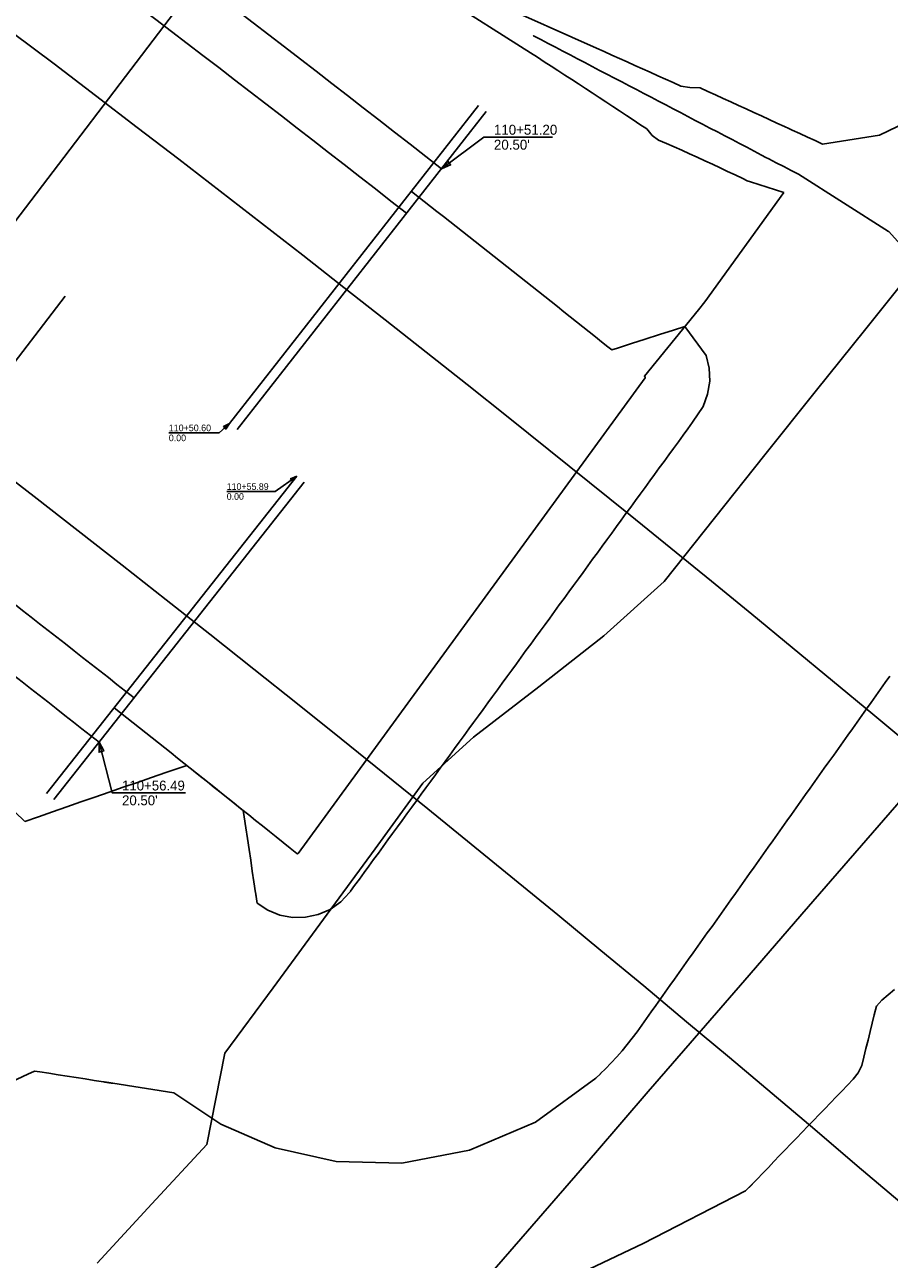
# Model space of a CAD drawing. Extents: x 1006695 to 1009377, y 1883329 to 1886115.
# Drawn here: x 1007771.4 to 1007824.9, y 1884757.7 to 1884834.1 of the extents above; entities that cross this region are included whole.
import ezdxf

# ---------------------------------------------------------------- set-up
doc = ezdxf.new("R2010")
doc.units = 0
for name, color, linetype in [('B_Bottom Cut', 7, 'Continuous'), ('B_Hatch', 7, 'Continuous'), ('B_Top Bench', 7, 'Continuous'), ('R_I-30 Information', 7, 'Continuous'), ('R_No Plot', 7, 'Continuous'), ('R_Prop Const Limits Cut', 7, 'Continuous'), ('R_Prop EOL', 7, 'Continuous'), ('R_Prop EOS', 7, 'Continuous'), ('R_Prop Guardrail', 7, 'Continuous')]:
    doc.layers.add(name, color=color, linetype=linetype)

msp = doc.modelspace()

# ---------------------------------------------------------------- linework, layer by layer
at = {"layer": 'B_Bottom Cut'}
for points in [[(1007824.824, 1884821.267), (1007824.815, 1884821.272), (1007824.806, 1884821.277), (1007819.236, 1884824.811), (1007818.779, 1884825.05), (1007818.323, 1884825.289), (1007817.867, 1884825.527), (1007817.41, 1884825.766), (1007817.228, 1884825.862), (1007816.954, 1884826.005), (1007816.498, 1884826.243), (1007816.042, 1884826.482), (1007815.586, 1884826.72), (1007815.13, 1884826.959), (1007814.674, 1884827.197), (1007814.218, 1884827.436), (1007813.763, 1884827.674), (1007813.307, 1884827.913), (1007812.851, 1884828.151), (1007812.396, 1884828.389), (1007811.94, 1884828.628), (1007811.485, 1884828.866), (1007811.029, 1884829.104), (1007810.574, 1884829.342), (1007810.119, 1884829.58), (1007809.664, 1884829.819), (1007809.208, 1884830.057), (1007808.753, 1884830.295), (1007808.298, 1884830.533), (1007807.843, 1884830.771), (1007807.388, 1884831.009), (1007806.934, 1884831.247), (1007806.479, 1884831.485), (1007806.024, 1884831.722), (1007805.569, 1884831.96), (1007805.115, 1884832.198), (1007804.66, 1884832.436), (1007804.206, 1884832.674), (1007803.751, 1884832.911), (1007803.297, 1884833.149), (1007802.842, 1884833.387), (1007802.824, 1884833.396)], [(1007827.368, 1884818.454), (1007824.824, 1884821.267)], [(1007770.535, 1884768.642), (1007771.552, 1884769.125), (1007771.957, 1884769.316), (1007772.294, 1884769.263), (1007772.855, 1884769.175), (1007773.416, 1884769.087), (1007773.977, 1884768.999), (1007774.539, 1884768.911), (1007775.101, 1884768.823), (1007775.663, 1884768.735), (1007776.226, 1884768.647), (1007776.237, 1884768.645), (1007776.248, 1884768.643), (1007776.259, 1884768.642), (1007776.271, 1884768.64), (1007776.282, 1884768.638), (1007776.293, 1884768.636), (1007776.304, 1884768.635), (1007776.316, 1884768.633), (1007776.327, 1884768.631), (1007776.338, 1884768.629), (1007776.349, 1884768.628), (1007776.361, 1884768.626), (1007776.372, 1884768.624), (1007776.383, 1884768.622), (1007776.394, 1884768.62), (1007776.406, 1884768.619), (1007776.417, 1884768.617), (1007776.428, 1884768.615), (1007776.439, 1884768.613), (1007776.451, 1884768.612), (1007776.462, 1884768.61), (1007776.473, 1884768.608), (1007776.484, 1884768.606), (1007776.496, 1884768.605), (1007776.507, 1884768.603), (1007776.518, 1884768.601), (1007776.529, 1884768.599), (1007776.541, 1884768.598), (1007776.552, 1884768.596), (1007776.563, 1884768.594), (1007776.574, 1884768.592), (1007776.586, 1884768.59), (1007776.597, 1884768.589), (1007776.608, 1884768.587), (1007776.619, 1884768.585), (1007776.631, 1884768.583), (1007776.642, 1884768.582), (1007776.653, 1884768.58), (1007776.664, 1884768.578), (1007776.676, 1884768.576), (1007776.687, 1884768.575), (1007776.698, 1884768.573), (1007776.709, 1884768.571), (1007776.721, 1884768.569), (1007776.732, 1884768.568), (1007776.743, 1884768.566), (1007776.809, 1884768.555), (1007780.586, 1884767.963), (1007783.487, 1884766.028), (1007786.851, 1884764.565), (1007790.621, 1884763.716), (1007794.686, 1884763.622), (1007798.878, 1884764.41), (1007802.97, 1884766.159), (1007806.696, 1884768.883), (1007806.979, 1884769.149), (1007806.986, 1884769.156), (1007806.993, 1884769.163), (1007807.297, 1884769.461), (1007807.648, 1884769.824), (1007807.989, 1884770.194), (1007808.32, 1884770.572), (1007808.64, 1884770.957), (1007808.95, 1884771.35), (1007809.25, 1884771.75), (1007809.543, 1884772.155), (1007809.832, 1884772.563), (1007810.122, 1884772.971), (1007810.411, 1884773.378), (1007810.701, 1884773.786), (1007810.991, 1884774.194), (1007811.28, 1884774.601), (1007811.57, 1884775.009), (1007811.859, 1884775.417), (1007812.149, 1884775.824), (1007812.439, 1884776.232), (1007812.728, 1884776.64), (1007813.018, 1884777.047), (1007813.307, 1884777.455), (1007813.597, 1884777.862), (1007813.887, 1884778.27), (1007814.176, 1884778.678), (1007814.466, 1884779.085), (1007814.755, 1884779.493), (1007815.045, 1884779.901), (1007815.335, 1884780.308), (1007815.624, 1884780.716), (1007815.914, 1884781.124), (1007816.203, 1884781.531), (1007816.493, 1884781.939), (1007816.783, 1884782.346), (1007817.072, 1884782.754), (1007817.362, 1884783.162), (1007817.651, 1884783.569), (1007817.941, 1884783.977), (1007818.231, 1884784.385), (1007818.52, 1884784.792), (1007818.81, 1884785.2), (1007819.099, 1884785.608), (1007819.389, 1884786.015), (1007819.679, 1884786.423), (1007819.968, 1884786.831), (1007820.258, 1884787.238), (1007820.547, 1884787.646), (1007820.837, 1884788.053), (1007821.127, 1884788.461), (1007821.416, 1884788.869), (1007821.706, 1884789.276), (1007821.995, 1884789.684), (1007822.285, 1884790.092), (1007822.575, 1884790.499), (1007822.864, 1884790.907), (1007823.154, 1884791.315), (1007823.443, 1884791.722), (1007823.733, 1884792.13), (1007824.023, 1884792.537), (1007824.312, 1884792.945), (1007824.602, 1884793.353), (1007824.891, 1884793.76)]]:
    msp.add_lwpolyline(points, dxfattribs=at)
at = {"layer": 'B_Hatch'}
for p, q in [((1007793.565, 1884838.118), (1007802.651, 1884832.325)), ((1007793.565, 1884838.118), (1007802.651, 1884832.325)), ((1007806.9, 1884829.575), (1007807.323, 1884829.297)), ((1007806.9, 1884829.575), (1007807.323, 1884829.297)), ((1007809.01, 1884828.18), (1007809.431, 1884827.9)), ((1007809.01, 1884828.18), (1007809.431, 1884827.9)), ((1007809.431, 1884827.9), (1007809.852, 1884827.619)), ((1007809.431, 1884827.9), (1007809.852, 1884827.619)), ((1007809.852, 1884827.619), (1007810.176, 1884827.217)), ((1007809.852, 1884827.619), (1007810.176, 1884827.217)), ((1007810.176, 1884827.217), (1007810.583, 1884826.919)), ((1007810.176, 1884827.217), (1007810.583, 1884826.919)), ((1007818.328, 1884823.681), (1007813.434, 1884816.929)), ((1007818.328, 1884823.681), (1007813.434, 1884816.929)), ((1007813.434, 1884816.929), (1007813.048, 1884816.433)), ((1007813.434, 1884816.929), (1007813.048, 1884816.433)), ((1007813.048, 1884816.433), (1007809.702, 1884812.32)), ((1007813.048, 1884816.433), (1007809.702, 1884812.32)), ((1007809.745, 1884812.224), (1007788.271, 1884782.782)), ((1007809.745, 1884812.224), (1007788.271, 1884782.782)), ((1007778.334, 1884787.182), (1007777.456, 1884786.879)), ((1007778.334, 1884787.182), (1007777.456, 1884786.879)), ((1007779.211, 1884787.485), (1007778.334, 1884787.182)), ((1007779.211, 1884787.485), (1007778.334, 1884787.182)), ((1007774.828, 1884785.968), (1007773.953, 1884785.664)), ((1007774.828, 1884785.968), (1007773.953, 1884785.664))]:
    msp.add_line(p, q, dxfattribs=at)
for points in [[(1007837.328, 1884833.526), (1007824.262, 1884827.234), (1007820.735, 1884826.678), (1007820.261, 1884826.896), (1007819.787, 1884827.114), (1007819.313, 1884827.333), (1007818.84, 1884827.551), (1007818.65, 1884827.638), (1007818.366, 1884827.769), (1007817.892, 1884827.987), (1007817.418, 1884828.204), (1007816.945, 1884828.422), (1007816.471, 1884828.639), (1007815.997, 1884828.857), (1007815.524, 1884829.074), (1007815.05, 1884829.291), (1007814.577, 1884829.508), (1007814.103, 1884829.725), (1007813.63, 1884829.942), (1007813.156, 1884830.159), (1007812.524, 1884830.176), (1007811.96, 1884830.277), (1007811.484, 1884830.491), (1007811.008, 1884830.704), (1007810.533, 1884830.917), (1007810.057, 1884831.13), (1007809.582, 1884831.343), (1007809.106, 1884831.556), (1007808.631, 1884831.769), (1007808.156, 1884831.982), (1007807.681, 1884832.195), (1007807.206, 1884832.408), (1007806.731, 1884832.62), (1007800.457, 1884835.431)], [(1007802.651, 1884832.325), (1007803.078, 1884832.052), (1007803.504, 1884831.779), (1007803.93, 1884831.505), (1007804.355, 1884831.231), (1007804.78, 1884830.956), (1007805.205, 1884830.681)], [(1007802.651, 1884832.325), (1007803.078, 1884832.052), (1007803.504, 1884831.779), (1007803.93, 1884831.505), (1007804.355, 1884831.231), (1007804.78, 1884830.956), (1007805.205, 1884830.681)], [(1007805.205, 1884830.681), (1007805.629, 1884830.405), (1007806.053, 1884830.129)], [(1007805.205, 1884830.681), (1007805.629, 1884830.405), (1007806.053, 1884830.129)], [(1007806.053, 1884830.129), (1007806.477, 1884829.852), (1007806.9, 1884829.575)], [(1007806.053, 1884830.129), (1007806.477, 1884829.852), (1007806.9, 1884829.575)], [(1007807.323, 1884829.297), (1007807.745, 1884829.019), (1007808.167, 1884828.74)], [(1007807.323, 1884829.297), (1007807.745, 1884829.019), (1007808.167, 1884828.74)], [(1007808.167, 1884828.74), (1007808.589, 1884828.46), (1007809.01, 1884828.18)], [(1007808.167, 1884828.74), (1007808.589, 1884828.46), (1007809.01, 1884828.18)], [(1007810.583, 1884826.919), (1007811.065, 1884826.714), (1007811.544, 1884826.507)], [(1007810.583, 1884826.919), (1007811.065, 1884826.714), (1007811.544, 1884826.507)], [(1007811.544, 1884826.507), (1007812.022, 1884826.297), (1007812.497, 1884826.085), (1007812.971, 1884825.871)], [(1007811.544, 1884826.507), (1007812.022, 1884826.297), (1007812.497, 1884826.085), (1007812.971, 1884825.871)], [(1007812.971, 1884825.871), (1007813.444, 1884825.655), (1007813.915, 1884825.437)], [(1007812.971, 1884825.871), (1007813.444, 1884825.655), (1007813.915, 1884825.437)], [(1007813.915, 1884825.437), (1007814.386, 1884825.217), (1007814.855, 1884824.996), (1007815.323, 1884824.774), (1007815.791, 1884824.551), (1007816.071, 1884824.417)], [(1007813.915, 1884825.437), (1007814.386, 1884825.217), (1007814.855, 1884824.996), (1007815.323, 1884824.774), (1007815.791, 1884824.551), (1007816.071, 1884824.417)], [(1007816.071, 1884824.417), (1007816.277, 1884824.351), (1007816.791, 1884824.185), (1007817.304, 1884824.019)], [(1007816.071, 1884824.417), (1007816.277, 1884824.351), (1007816.791, 1884824.185), (1007817.304, 1884824.019)], [(1007817.304, 1884824.019), (1007817.817, 1884823.85), (1007818.328, 1884823.681)], [(1007817.304, 1884824.019), (1007817.817, 1884823.85), (1007818.328, 1884823.681)], [(1007771.354, 1884784.76), (1007767.582, 1884788.381), (1007767.14, 1884788.771)], [(1007771.354, 1884784.76), (1007767.582, 1884788.381), (1007767.14, 1884788.771)], [(1007781.38, 1884788.232), (1007780.09, 1884787.788), (1007779.211, 1884787.485)], [(1007781.38, 1884788.232), (1007780.09, 1884787.788), (1007779.211, 1884787.485)], [(1007777.456, 1884786.879), (1007776.58, 1884786.576), (1007775.704, 1884786.272), (1007774.828, 1884785.968)], [(1007777.456, 1884786.879), (1007776.58, 1884786.576), (1007775.704, 1884786.272), (1007774.828, 1884785.968)], [(1007773.953, 1884785.664), (1007773.079, 1884785.36), (1007772.205, 1884785.056), (1007771.354, 1884784.76)], [(1007773.953, 1884785.664), (1007773.079, 1884785.36), (1007772.205, 1884785.056), (1007771.354, 1884784.76)], [(1007803.812, 1884755.882), (1007809.624, 1884758.641), (1007815.964, 1884761.891), (1007816.381, 1884762.316), (1007816.674, 1884762.622), (1007817.023, 1884762.986), (1007817.373, 1884763.35), (1007817.722, 1884763.714), (1007818.072, 1884764.078), (1007818.422, 1884764.441), (1007818.772, 1884764.804), (1007819.123, 1884765.168), (1007819.473, 1884765.531), (1007819.824, 1884765.894), (1007820.175, 1884766.257), (1007820.525, 1884766.621), (1007820.876, 1884766.984), (1007821.226, 1884767.347), (1007821.577, 1884767.71), (1007821.927, 1884768.073), (1007822.278, 1884768.437), (1007822.62, 1884768.806), (1007822.934, 1884769.196), (1007823.154, 1884769.654), (1007823.283, 1884770.179), (1007823.412, 1884770.704), (1007823.541, 1884771.228), (1007823.67, 1884771.753), (1007823.799, 1884772.278), (1007823.928, 1884772.803), (1007824.058, 1884773.326), (1007824.404, 1884773.693), (1007824.788, 1884774.032), (1007825.171, 1884774.371)]]:
    msp.add_lwpolyline(points, dxfattribs=at)
for centre, radius, start, end in [((1006901.082, 1883681.489), 1450.644, 51.21645, 51.218202), ((1006901.082, 1883681.489), 1450.644, 51.21645, 51.218202), ((1007809.705, 1884812.253), 0.05, 323.89384, 51.21645), ((1007809.705, 1884812.253), 0.05, 323.89384, 51.21645), ((1006901.082, 1883681.489), 1414.144, 51.147484, 51.501427), ((1006901.082, 1883681.489), 1414.144, 51.147484, 51.501427), ((1007788.231, 1884782.812), 0.05, 231.14748, 323.89384), ((1007788.231, 1884782.812), 0.05, 231.14748, 323.89384)]:
    msp.add_arc(centre, radius, start, end, dxfattribs=at)
at = {"layer": 'B_Top Bench'}
for points in [[(1007812.24, 1884815.411), (1007812.223, 1884815.406), (1007812.205, 1884815.4), (1007811.495, 1884815.172), (1007810.628, 1884814.892), (1007809.761, 1884814.612), (1007808.895, 1884814.332), (1007808.029, 1884814.051), (1007807.683, 1884813.939), (1007807.449, 1884814.126), (1007807.058, 1884814.439), (1007806.668, 1884814.751), (1007806.277, 1884815.063), (1007805.886, 1884815.375), (1007805.496, 1884815.687), (1007805.105, 1884815.998), (1007804.713, 1884816.31), (1007804.322, 1884816.621), (1007803.931, 1884816.932), (1007803.54, 1884817.244), (1007803.148, 1884817.555), (1007802.756, 1884817.865), (1007802.365, 1884818.176), (1007801.973, 1884818.487), (1007801.581, 1884818.797), (1007801.189, 1884819.108), (1007800.797, 1884819.418), (1007800.404, 1884819.728), (1007800.012, 1884820.038), (1007799.62, 1884820.347), (1007799.227, 1884820.657), (1007798.834, 1884820.967), (1007798.441, 1884821.276), (1007798.049, 1884821.585), (1007797.655, 1884821.894), (1007797.262, 1884822.203), (1007796.869, 1884822.512), (1007796.476, 1884822.821), (1007796.082, 1884823.129), (1007795.689, 1884823.438), (1007795.295, 1884823.746), (1007795.279, 1884823.758)], [(1007776.885, 1884791.792), (1007777.277, 1884791.482), (1007777.67, 1884791.172), (1007778.062, 1884790.862), (1007778.454, 1884790.552), (1007778.846, 1884790.242), (1007779.238, 1884789.932), (1007779.63, 1884789.621), (1007780.022, 1884789.31), (1007780.414, 1884788.999), (1007780.805, 1884788.688), (1007781.197, 1884788.377), (1007781.588, 1884788.066), (1007781.979, 1884787.755), (1007782.37, 1884787.443), (1007782.761, 1884787.132), (1007783.152, 1884786.82), (1007783.543, 1884786.508), (1007783.933, 1884786.196), (1007784.324, 1884785.883), (1007784.714, 1884785.571), (1007784.87, 1884785.446), (1007784.932, 1884785.043), (1007785.035, 1884784.372), (1007785.137, 1884783.701), (1007785.239, 1884783.029), (1007785.34, 1884782.358), (1007785.441, 1884781.687), (1007785.542, 1884781.016), (1007785.643, 1884780.345), (1007785.645, 1884780.332), (1007785.647, 1884780.319), (1007785.649, 1884780.305), (1007785.651, 1884780.292), (1007785.653, 1884780.278), (1007785.655, 1884780.265), (1007785.657, 1884780.251), (1007785.659, 1884780.238), (1007785.661, 1884780.225), (1007785.663, 1884780.211), (1007785.665, 1884780.198), (1007785.667, 1884780.184), (1007785.669, 1884780.171), (1007785.671, 1884780.157), (1007785.673, 1884780.144), (1007785.675, 1884780.131), (1007785.677, 1884780.117), (1007785.679, 1884780.104), (1007785.681, 1884780.09), (1007785.683, 1884780.077), (1007785.685, 1884780.064), (1007785.687, 1884780.05), (1007785.689, 1884780.037), (1007785.691, 1884780.023), (1007785.693, 1884780.01), (1007785.695, 1884779.996), (1007785.697, 1884779.983), (1007785.699, 1884779.97), (1007785.701, 1884779.956), (1007785.703, 1884779.943), (1007785.705, 1884779.929), (1007785.707, 1884779.916), (1007785.709, 1884779.903), (1007785.711, 1884779.889), (1007785.713, 1884779.876), (1007785.715, 1884779.862), (1007785.717, 1884779.849), (1007785.719, 1884779.835), (1007785.721, 1884779.822), (1007785.723, 1884779.809), (1007785.725, 1884779.795), (1007785.727, 1884779.782), (1007785.729, 1884779.768), (1007785.731, 1884779.755), (1007785.733, 1884779.742), (1007785.735, 1884779.728), (1007785.745, 1884779.708), (1007786.407, 1884779.268), (1007787.144, 1884778.967), (1007787.929, 1884778.819), (1007788.729, 1884778.829), (1007789.514, 1884778.999), (1007790.25, 1884779.322), (1007790.909, 1884779.786), (1007791.464, 1884780.373), (1007791.509, 1884780.432), (1007791.514, 1884780.44), (1007791.52, 1884780.449), (1007791.768, 1884780.788), (1007792.063, 1884781.192), (1007792.357, 1884781.596), (1007792.652, 1884782), (1007792.946, 1884782.404), (1007793.241, 1884782.808), (1007793.536, 1884783.212), (1007793.83, 1884783.616), (1007794.125, 1884784.02), (1007794.42, 1884784.424), (1007794.714, 1884784.827), (1007795.009, 1884785.231), (1007795.304, 1884785.635), (1007795.598, 1884786.039), (1007795.893, 1884786.443), (1007796.188, 1884786.847), (1007796.482, 1884787.251), (1007796.777, 1884787.655), (1007797.071, 1884788.059), (1007797.366, 1884788.463), (1007797.661, 1884788.867), (1007797.955, 1884789.271), (1007798.25, 1884789.675), (1007798.545, 1884790.079), (1007798.839, 1884790.483), (1007799.134, 1884790.887), (1007799.429, 1884791.291), (1007799.723, 1884791.695), (1007800.018, 1884792.099), (1007800.312, 1884792.503), (1007800.607, 1884792.907), (1007800.902, 1884793.311), (1007801.196, 1884793.715), (1007801.491, 1884794.119), (1007801.786, 1884794.523), (1007802.08, 1884794.927), (1007802.375, 1884795.331), (1007802.67, 1884795.734), (1007802.964, 1884796.138), (1007803.259, 1884796.542), (1007803.554, 1884796.946), (1007803.848, 1884797.35), (1007804.143, 1884797.754), (1007804.437, 1884798.158), (1007804.732, 1884798.562), (1007805.027, 1884798.966), (1007805.321, 1884799.37), (1007805.616, 1884799.774), (1007805.911, 1884800.178), (1007806.205, 1884800.582), (1007806.5, 1884800.986), (1007806.795, 1884801.39), (1007807.089, 1884801.794), (1007807.384, 1884802.198), (1007807.679, 1884802.602), (1007807.973, 1884803.006), (1007808.268, 1884803.41), (1007808.562, 1884803.814), (1007808.857, 1884804.218), (1007809.152, 1884804.622), (1007809.446, 1884805.026), (1007809.741, 1884805.43), (1007810.036, 1884805.834), (1007810.33, 1884806.238), (1007810.625, 1884806.641), (1007810.92, 1884807.045), (1007811.214, 1884807.449), (1007811.509, 1884807.853), (1007811.804, 1884808.257), (1007812.098, 1884808.661), (1007812.393, 1884809.065), (1007812.687, 1884809.469), (1007813.33, 1884810.446), (1007813.616, 1884811.203), (1007813.747, 1884812.001), (1007813.717, 1884812.809), (1007813.526, 1884813.595), (1007812.205, 1884815.4)]]:
    msp.add_lwpolyline(points, dxfattribs=at)
at = {"layer": 'R_I-30 Information'}
for points in [[(1007875.105, 1884843.265), (1007871.832, 1884839.487), (1007868.558, 1884835.708), (1007865.284, 1884831.928), (1007862.01, 1884828.148), (1007858.736, 1884824.369), (1007855.463, 1884820.589), (1007852.189, 1884816.81), (1007848.915, 1884813.031), (1007845.642, 1884809.251), (1007842.368, 1884805.472), (1007839.094, 1884801.693), (1007835.821, 1884797.913), (1007832.546, 1884794.133), (1007829.272, 1884790.353), (1007825.999, 1884786.574), (1007822.726, 1884782.796), (1007819.453, 1884779.017), (1007816.179, 1884775.238), (1007813.22, 1884771.818), (1007809.946, 1884768.039), (1007806.672, 1884764.259), (1007803.144, 1884760.189), (1007799.87, 1884756.41)], [(1007775.84, 1884757.42), (1007779.231, 1884761.097), (1007782.635, 1884764.768), (1007783.743, 1884770.43), (1007786.732, 1884774.456), (1007790.074, 1884779.014), (1007793.039, 1884783.068), (1007796.001, 1884787.126), (1007799.138, 1884789.975), (1007803.175, 1884793.095), (1007807.183, 1884796.239), (1007810.93, 1884799.605), (1007814.032, 1884803.533), (1007817.147, 1884807.45), (1007820.275, 1884811.358), (1007823.412, 1884815.255), (1007826.538, 1884819.162), (1007829.741, 1884823.002), (1007833.002, 1884826.793), (1007836.41, 1884830.456), (1007839.605, 1884834.304)]]:
    msp.add_lwpolyline(points, dxfattribs=at)
at = {"layer": 'R_No Plot'}
for p, q in [((1007784.825, 1884840.366), (1007769.666, 1884820.486)), ((1007799.438, 1884829.075), (1007784.028, 1884809.389)), ((1007799.919, 1884828.698), (1007784.5, 1884809.019)), ((1007800.391, 1884827.107), (1007804.019, 1884827.107)), ((1007758.633, 1884797.448), (1007773.866, 1884817.271)), ((1007780.271, 1884808.81), (1007782.976, 1884808.81)), ((1007772.704, 1884786.492), (1007788.187, 1884806.121)), ((1007773.167, 1884786.127), (1007788.658, 1884805.749)), ((1007783.857, 1884805.18), (1007786.455, 1884805.18)), ((1007777.379, 1884786.525), (1007781.299, 1884786.525))]:
    msp.add_line(p, q, dxfattribs=at)
for points in [[(1007797.144, 1884825.156), (1007799.775, 1884827.107), (1007800.391, 1884827.107)], [(1007784.028, 1884809.389), (1007783.387, 1884808.81), (1007782.976, 1884808.81)], [(1007788.187, 1884806.121), (1007786.863, 1884805.18), (1007786.455, 1884805.18)], [(1007775.956, 1884789.659), (1007776.768, 1884786.525), (1007777.379, 1884786.525)]]:
    msp.add_lwpolyline(points, dxfattribs=at)
for points in [[(1007797.144, 1884825.156), (1007797.535, 1884825.633), (1007797.713, 1884825.393)], [(1007784.028, 1884809.389), (1007783.799, 1884809.048), (1007783.665, 1884809.196)], [(1007788.187, 1884806.121), (1007787.922, 1884805.811), (1007787.807, 1884805.972)], [(1007775.956, 1884789.659), (1007776.248, 1884789.122), (1007775.961, 1884789.048)]]:
    msp.add_lwpolyline(points, close=True, dxfattribs=at)
at = {"layer": 'R_Prop Const Limits Cut'}
for points in [[(1007800.457, 1884835.431), (1007806.731, 1884832.62), (1007807.206, 1884832.408), (1007807.681, 1884832.195), (1007808.156, 1884831.982), (1007808.631, 1884831.769), (1007809.106, 1884831.556), (1007809.582, 1884831.343), (1007810.057, 1884831.13), (1007810.533, 1884830.917), (1007811.008, 1884830.704), (1007811.484, 1884830.491), (1007811.96, 1884830.277), (1007812.524, 1884830.176), (1007813.156, 1884830.159), (1007813.63, 1884829.942), (1007814.103, 1884829.725), (1007814.577, 1884829.508), (1007815.05, 1884829.291), (1007815.524, 1884829.074), (1007815.997, 1884828.857), (1007816.471, 1884828.639), (1007816.945, 1884828.422), (1007817.418, 1884828.204), (1007817.892, 1884827.987), (1007818.366, 1884827.769), (1007818.65, 1884827.638), (1007818.84, 1884827.551), (1007819.313, 1884827.333), (1007819.787, 1884827.114), (1007820.261, 1884826.896), (1007820.735, 1884826.678), (1007824.262, 1884827.234), (1007837.328, 1884833.526)], [(1007825.171, 1884774.371), (1007824.788, 1884774.032), (1007824.404, 1884773.693), (1007824.058, 1884773.326), (1007823.928, 1884772.803), (1007823.799, 1884772.278), (1007823.67, 1884771.753), (1007823.541, 1884771.228), (1007823.412, 1884770.704), (1007823.283, 1884770.179), (1007823.154, 1884769.654), (1007822.934, 1884769.196), (1007822.62, 1884768.806), (1007822.278, 1884768.437), (1007821.927, 1884768.073), (1007821.577, 1884767.71), (1007821.226, 1884767.347), (1007820.876, 1884766.984), (1007820.525, 1884766.621), (1007820.175, 1884766.257), (1007819.824, 1884765.894), (1007819.473, 1884765.531), (1007819.123, 1884765.168), (1007818.772, 1884764.804), (1007818.422, 1884764.441), (1007818.072, 1884764.078), (1007817.722, 1884763.714), (1007817.373, 1884763.35), (1007817.023, 1884762.986), (1007816.674, 1884762.622), (1007816.381, 1884762.316), (1007816.374, 1884762.308), (1007816.367, 1884762.301), (1007815.964, 1884761.891), (1007809.624, 1884758.641), (1007803.812, 1884755.882)]]:
    msp.add_lwpolyline(points, dxfattribs=at)
at = {"layer": 'R_Prop EOL'}
for radius, start in [(1443.394, 37.045062), (1421.394, 35.651642)]:
    msp.add_arc((1006901.082, 1883681.489), radius, start, 53.471968, dxfattribs=at)
at = {"layer": 'R_Prop EOS'}
for radius, start, end in [(1452.894, 51.921348, 53.471968), (1411.894, 51.709748, 53.459748)]:
    msp.add_arc((1006901.082, 1883681.489), radius, start, end, dxfattribs=at)
at = {"layer": 'R_Prop Guardrail'}
for radius, start, end in [(1449.394, 51.921348, 53.471968), (1415.394, 51.709748, 53.459748)]:
    msp.add_arc((1006901.082, 1883681.489), radius, start, end, dxfattribs=at)

# ---------------------------------------------------------------- texts
at = {"layer": 'R_No Plot'}
for s, height, p in [('110+51.20', 0.6168, (1007800.391, 1884827.262)), ("20.50'", 0.6168, (1007800.391, 1884826.336)), ('110+50.60', 0.4114, (1007780.271, 1884808.912)), ('0.00', 0.4114, (1007780.271, 1884808.295)), ('110+55.89', 0.4079, (1007783.857, 1884805.282)), ('0.00', 0.4079, (1007783.857, 1884804.671)), ('110+56.49', 0.6111, (1007777.379, 1884786.678)), ("20.50'", 0.6111, (1007777.379, 1884785.761))]:
    msp.add_text(s, height=height, dxfattribs=at).set_placement(p)

doc.saveas('drawing.dxf')
